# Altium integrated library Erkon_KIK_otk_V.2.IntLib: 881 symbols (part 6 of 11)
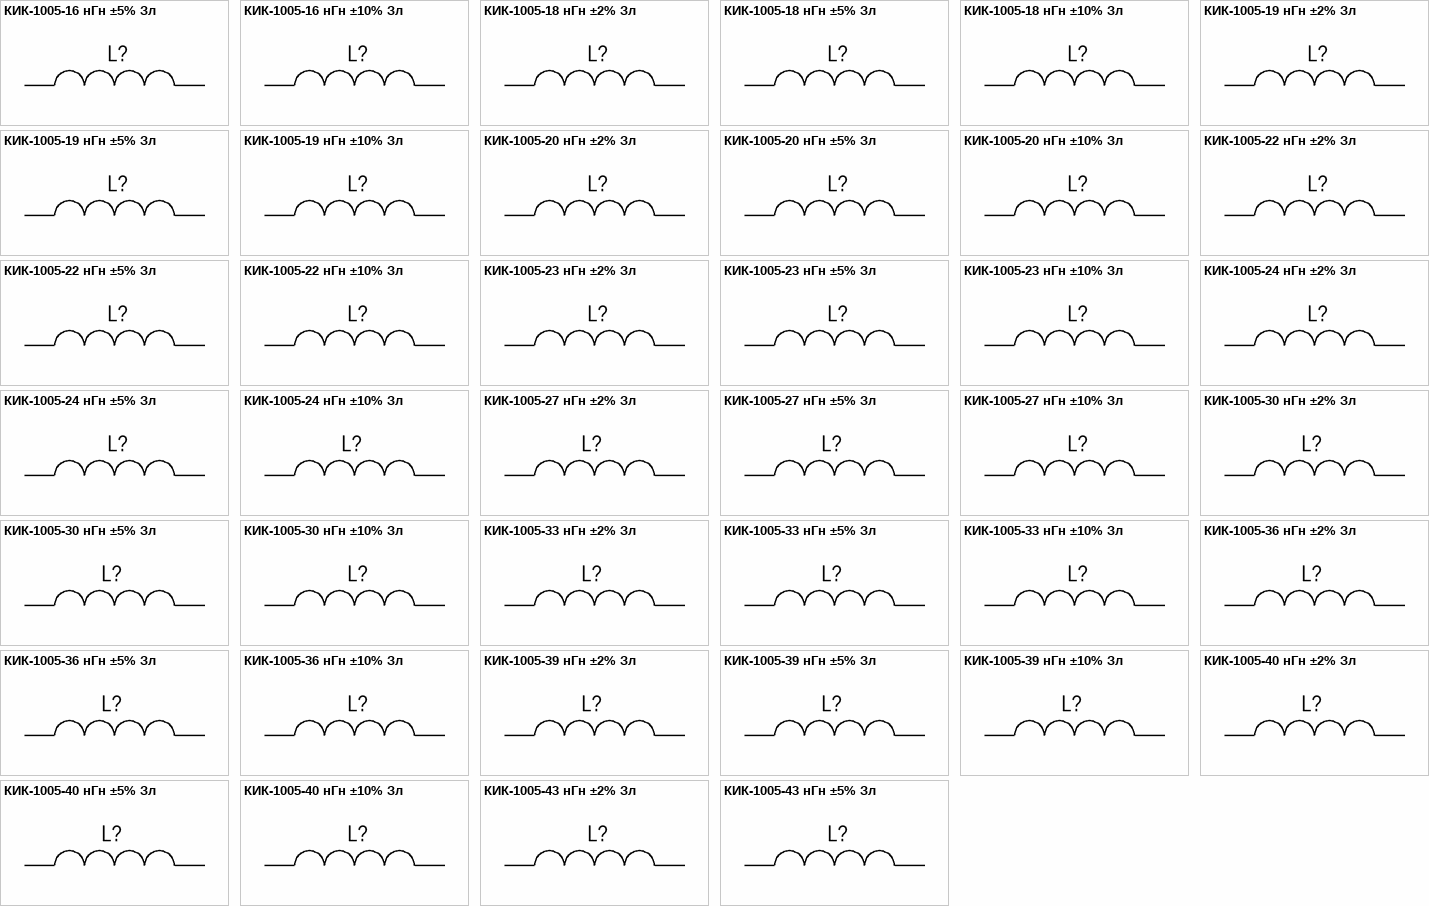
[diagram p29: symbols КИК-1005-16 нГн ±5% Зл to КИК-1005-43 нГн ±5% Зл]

## КИК-1005-20 нГн ±2% Зл
designator L?, comment 20 нГн ±2%  (value not drawn)
Катушка индуктивности с керамическим сердечником и золотым покрытием контактных площадок; Номиналиная индуктивность: 20 нГн; Добротность, не менее: 25; Резонансная частота, не менее: 3.00 ГГц; Сопротивление обмотки постоянноми току, не более: 0.25 Ом; Допустимый ток обмотки: 420 мА; Изготовитель: АО "НПО "ЭРКОН"; Диапазон рабочих температур: от -60 до +125 ℃; Технология монтажа: SMT; Типоразмер: 1005 (0402); Упаковка: Катушка и лента
footprint КИК-1005_Зл (Катушка индуктивности с керамическим сердечником типоразмер 1005(0402))
pins: 1, 2

## КИК-1005-20 нГн ±5% Зл
designator L?, comment 20 нГн ±5%  (value not drawn)
Катушка индуктивности с керамическим сердечником и золотым покрытием контактных площадок; Номиналиная индуктивность: 20 нГн; Добротность, не менее: 25; Резонансная частота, не менее: 3.00 ГГц; Сопротивление обмотки постоянноми току, не более: 0.25 Ом; Допустимый ток обмотки: 420 мА; Изготовитель: АО "НПО "ЭРКОН"; Диапазон рабочих температур: от -60 до +125 ℃; Технология монтажа: SMT; Типоразмер: 1005 (0402); Упаковка: Катушка и лента
footprint КИК-1005_Зл (Катушка индуктивности с керамическим сердечником типоразмер 1005(0402))
pins: 1, 2

## КИК-1005-20 нГн ±10% Зл
designator L?, comment 20 нГн ±10%  (value not drawn)
Катушка индуктивности с керамическим сердечником и золотым покрытием контактных площадок; Номиналиная индуктивность: 20 нГн; Добротность, не менее: 25; Резонансная частота, не менее: 3.00 ГГц; Сопротивление обмотки постоянноми току, не более: 0.25 Ом; Допустимый ток обмотки: 420 мА; Изготовитель: АО "НПО "ЭРКОН"; Диапазон рабочих температур: от -60 до +125 ℃; Технология монтажа: SMT; Типоразмер: 1005 (0402); Упаковка: Катушка и лента
footprint КИК-1005_Зл (Катушка индуктивности с керамическим сердечником типоразмер 1005(0402))
pins: 1, 2

## КИК-1005-22 нГн ±2% Зл
designator L?, comment 22 нГн ±2%  (value not drawn)
Катушка индуктивности с керамическим сердечником и золотым покрытием контактных площадок; Номиналиная индуктивность: 22 нГн; Добротность, не менее: 25; Резонансная частота, не менее: 2.80 ГГц; Сопротивление обмотки постоянноми току, не более: 0.30 Ом; Допустимый ток обмотки: 400 мА; Изготовитель: АО "НПО "ЭРКОН"; Диапазон рабочих температур: от -60 до +125 ℃; Технология монтажа: SMT; Типоразмер: 1005 (0402); Упаковка: Катушка и лента
footprint КИК-1005_Зл (Катушка индуктивности с керамическим сердечником типоразмер 1005(0402))
pins: 1, 2

## КИК-1005-22 нГн ±5% Зл
designator L?, comment 22 нГн ±5%  (value not drawn)
Катушка индуктивности с керамическим сердечником и золотым покрытием контактных площадок; Номиналиная индуктивность: 22 нГн; Добротность, не менее: 25; Резонансная частота, не менее: 2.80 ГГц; Сопротивление обмотки постоянноми току, не более: 0.30 Ом; Допустимый ток обмотки: 400 мА; Изготовитель: АО "НПО "ЭРКОН"; Диапазон рабочих температур: от -60 до +125 ℃; Технология монтажа: SMT; Типоразмер: 1005 (0402); Упаковка: Катушка и лента
footprint КИК-1005_Зл (Катушка индуктивности с керамическим сердечником типоразмер 1005(0402))
pins: 1, 2

## КИК-1005-22 нГн ±10% Зл
designator L?, comment 22 нГн ±10%  (value not drawn)
Катушка индуктивности с керамическим сердечником и золотым покрытием контактных площадок; Номиналиная индуктивность: 22 нГн; Добротность, не менее: 25; Резонансная частота, не менее: 2.80 ГГц; Сопротивление обмотки постоянноми току, не более: 0.30 Ом; Допустимый ток обмотки: 400 мА; Изготовитель: АО "НПО "ЭРКОН"; Диапазон рабочих температур: от -60 до +125 ℃; Технология монтажа: SMT; Типоразмер: 1005 (0402); Упаковка: Катушка и лента
footprint КИК-1005_Зл (Катушка индуктивности с керамическим сердечником типоразмер 1005(0402))
pins: 1, 2

## КИК-1005-23 нГн ±2% Зл
designator L?, comment 23 нГн ±2%  (value not drawn)
Катушка индуктивности с керамическим сердечником и золотым покрытием контактных площадок; Номиналиная индуктивность: 23 нГн; Добротность, не менее: 25; Резонансная частота, не менее: 2.72ГГц; Сопротивление обмотки постоянноми току, не более: 0.30 Ом; Допустимый ток обмотки: 400 мА; Изготовитель: АО "НПО "ЭРКОН"; Диапазон рабочих температур: от -60 до +125 ℃; Технология монтажа: SMT; Типоразмер: 1005 (0402); Упаковка: Катушка и лента
footprint КИК-1005_Зл (Катушка индуктивности с керамическим сердечником типоразмер 1005(0402))
pins: 1, 2

## КИК-1005-23 нГн ±5% Зл
designator L?, comment 23 нГн ±5%  (value not drawn)
Катушка индуктивности с керамическим сердечником и золотым покрытием контактных площадок; Номиналиная индуктивность: 23 нГн; Добротность, не менее: 25; Резонансная частота, не менее: 2.72ГГц; Сопротивление обмотки постоянноми току, не более: 0.30 Ом; Допустимый ток обмотки: 400 мА; Изготовитель: АО "НПО "ЭРКОН"; Диапазон рабочих температур: от -60 до +125 ℃; Технология монтажа: SMT; Типоразмер: 1005 (0402); Упаковка: Катушка и лента
footprint КИК-1005_Зл (Катушка индуктивности с керамическим сердечником типоразмер 1005(0402))
pins: 1, 2

## КИК-1005-23 нГн ±10% Зл
designator L?, comment 23 нГн ±10%  (value not drawn)
Катушка индуктивности с керамическим сердечником и золотым покрытием контактных площадок; Номиналиная индуктивность: 23 нГн; Добротность, не менее: 25; Резонансная частота, не менее: 2.72ГГц; Сопротивление обмотки постоянноми току, не более: 0.30 Ом; Допустимый ток обмотки: 400 мА; Изготовитель: АО "НПО "ЭРКОН"; Диапазон рабочих температур: от -60 до +125 ℃; Технология монтажа: SMT; Типоразмер: 1005 (0402); Упаковка: Катушка и лента
footprint КИК-1005_Зл (Катушка индуктивности с керамическим сердечником типоразмер 1005(0402))
pins: 1, 2

## КИК-1005-24 нГн ±2% Зл
designator L?, comment 24 нГн ±2%  (value not drawn)
Катушка индуктивности с керамическим сердечником и золотым покрытием контактных площадок; Номиналиная индуктивность: 24 нГн; Добротность, не менее: 25; Резонансная частота, не менее: 2.70 ГГц; Сопротивление обмотки постоянноми току, не более: 0.30 Ом; Допустимый ток обмотки: 400 мА; Изготовитель: АО "НПО "ЭРКОН"; Диапазон рабочих температур: от -60 до +125 ℃; Технология монтажа: SMT; Типоразмер: 1005 (0402); Упаковка: Катушка и лента
footprint КИК-1005_Зл (Катушка индуктивности с керамическим сердечником типоразмер 1005(0402))
pins: 1, 2

## КИК-1005-24 нГн ±5% Зл
designator L?, comment 24 нГн ±5%  (value not drawn)
Катушка индуктивности с керамическим сердечником и золотым покрытием контактных площадок; Номиналиная индуктивность: 24 нГн; Добротность, не менее: 25; Резонансная частота, не менее: 2.70 ГГц; Сопротивление обмотки постоянноми току, не более: 0.30 Ом; Допустимый ток обмотки: 400 мА; Изготовитель: АО "НПО "ЭРКОН"; Диапазон рабочих температур: от -60 до +125 ℃; Технология монтажа: SMT; Типоразмер: 1005 (0402); Упаковка: Катушка и лента
footprint КИК-1005_Зл (Катушка индуктивности с керамическим сердечником типоразмер 1005(0402))
pins: 1, 2

## КИК-1005-24 нГн ±10% Зл
designator L?, comment 24 нГн ±10%  (value not drawn)
Катушка индуктивности с керамическим сердечником и золотым покрытием контактных площадок; Номиналиная индуктивность: 24 нГн; Добротность, не менее: 25; Резонансная частота, не менее: 2.70 ГГц; Сопротивление обмотки постоянноми току, не более: 0.30 Ом; Допустимый ток обмотки: 400 мА; Изготовитель: АО "НПО "ЭРКОН"; Диапазон рабочих температур: от -60 до +125 ℃; Технология монтажа: SMT; Типоразмер: 1005 (0402); Упаковка: Катушка и лента
footprint КИК-1005_Зл (Катушка индуктивности с керамическим сердечником типоразмер 1005(0402))
pins: 1, 2

## КИК-1005-27 нГн ±2% Зл
designator L?, comment 27 нГн ±2%  (value not drawn)
Катушка индуктивности с керамическим сердечником и золотым покрытием контактных площадок; Номиналиная индуктивность: 27 нГн; Добротность, не менее: 25; Резонансная частота, не менее: 2.48 ГГц; Сопротивление обмотки постоянноми току, не более: 0.30 Ом; Допустимый ток обмотки: 400 мА; Изготовитель: АО "НПО "ЭРКОН"; Диапазон рабочих температур: от -60 до +125 ℃; Технология монтажа: SMT; Типоразмер: 1005 (0402); Упаковка: Катушка и лента
footprint КИК-1005_Зл (Катушка индуктивности с керамическим сердечником типоразмер 1005(0402))
pins: 1, 2

## КИК-1005-27 нГн ±5% Зл
designator L?, comment 27 нГн ±5%  (value not drawn)
Катушка индуктивности с керамическим сердечником и золотым покрытием контактных площадок; Номиналиная индуктивность: 27 нГн; Добротность, не менее: 25; Резонансная частота, не менее: 2.48 ГГц; Сопротивление обмотки постоянноми току, не более: 0.30 Ом; Допустимый ток обмотки: 400 мА; Изготовитель: АО "НПО "ЭРКОН"; Диапазон рабочих температур: от -60 до +125 ℃; Технология монтажа: SMT; Типоразмер: 1005 (0402); Упаковка: Катушка и лента
footprint КИК-1005_Зл (Катушка индуктивности с керамическим сердечником типоразмер 1005(0402))
pins: 1, 2

## КИК-1005-27 нГн ±10% Зл
designator L?, comment 27 нГн ±10%  (value not drawn)
Катушка индуктивности с керамическим сердечником и золотым покрытием контактных площадок; Номиналиная индуктивность: 27 нГн; Добротность, не менее: 25; Резонансная частота, не менее: 2.48 ГГц; Сопротивление обмотки постоянноми току, не более: 0.30 Ом; Допустимый ток обмотки: 400 мА; Изготовитель: АО "НПО "ЭРКОН"; Диапазон рабочих температур: от -60 до +125 ℃; Технология монтажа: SMT; Типоразмер: 1005 (0402); Упаковка: Катушка и лента
footprint КИК-1005_Зл (Катушка индуктивности с керамическим сердечником типоразмер 1005(0402))
pins: 1, 2

## КИК-1005-30 нГн ±2% Зл
designator L?, comment 30 нГн ±2%  (value not drawn)
Катушка индуктивности с керамическим сердечником и золотым покрытием контактных площадок; Номиналиная индуктивность: 30 нГн; Добротность, не менее: 25; Резонансная частота, не менее: 2.35 ГГц; Сопротивление обмотки постоянноми току, не более: 0.30 Ом; Допустимый ток обмотки: 400 мА; Изготовитель: АО "НПО "ЭРКОН"; Диапазон рабочих температур: от -60 до +125 ℃; Технология монтажа: SMT; Типоразмер: 1005 (0402); Упаковка: Катушка и лента
footprint КИК-1005_Зл (Катушка индуктивности с керамическим сердечником типоразмер 1005(0402))
pins: 1, 2

## КИК-1005-30 нГн ±5% Зл
designator L?, comment 30 нГн ±5%  (value not drawn)
Катушка индуктивности с керамическим сердечником и золотым покрытием контактных площадок; Номиналиная индуктивность: 30 нГн; Добротность, не менее: 25; Резонансная частота, не менее: 2.35 ГГц; Сопротивление обмотки постоянноми току, не более: 0.30 Ом; Допустимый ток обмотки: 400 мА; Изготовитель: АО "НПО "ЭРКОН"; Диапазон рабочих температур: от -60 до +125 ℃; Технология монтажа: SMT; Типоразмер: 1005 (0402); Упаковка: Катушка и лента
footprint КИК-1005_Зл (Катушка индуктивности с керамическим сердечником типоразмер 1005(0402))
pins: 1, 2

## КИК-1005-30 нГн ±10% Зл
designator L?, comment 30 нГн ±10%  (value not drawn)
Катушка индуктивности с керамическим сердечником и золотым покрытием контактных площадок; Номиналиная индуктивность: 30 нГн; Добротность, не менее: 25; Резонансная частота, не менее: 2.35 ГГц; Сопротивление обмотки постоянноми току, не более: 0.30 Ом; Допустимый ток обмотки: 400 мА; Изготовитель: АО "НПО "ЭРКОН"; Диапазон рабочих температур: от -60 до +125 ℃; Технология монтажа: SMT; Типоразмер: 1005 (0402); Упаковка: Катушка и лента
footprint КИК-1005_Зл (Катушка индуктивности с керамическим сердечником типоразмер 1005(0402))
pins: 1, 2

## КИК-1005-33 нГн ±2% Зл
designator L?, comment 33 нГн ±2%  (value not drawn)
Катушка индуктивности с керамическим сердечником и золотым покрытием контактных площадок; Номиналиная индуктивность: 33 нГн; Добротность, не менее: 25; Резонансная частота, не менее: 2.35 ГГц; Сопротивление обмотки постоянноми току, не более: 0.30 Ом; Допустимый ток обмотки: 400 мА; Изготовитель: АО "НПО "ЭРКОН"; Диапазон рабочих температур: от -60 до +125 ℃; Технология монтажа: SMT; Типоразмер: 1005 (0402); Упаковка: Катушка и лента
footprint КИК-1005_Зл (Катушка индуктивности с керамическим сердечником типоразмер 1005(0402))
pins: 1, 2

## КИК-1005-33 нГн ±5% Зл
designator L?, comment 33 нГн ±5%  (value not drawn)
Катушка индуктивности с керамическим сердечником и золотым покрытием контактных площадок; Номиналиная индуктивность: 33 нГн; Добротность, не менее: 25; Резонансная частота, не менее: 2.35 ГГц; Сопротивление обмотки постоянноми току, не более: 0.30 Ом; Допустимый ток обмотки: 400 мА; Изготовитель: АО "НПО "ЭРКОН"; Диапазон рабочих температур: от -60 до +125 ℃; Технология монтажа: SMT; Типоразмер: 1005 (0402); Упаковка: Катушка и лента
footprint КИК-1005_Зл (Катушка индуктивности с керамическим сердечником типоразмер 1005(0402))
pins: 1, 2

## КИК-1005-33 нГн ±10% Зл
designator L?, comment 33 нГн ±10%  (value not drawn)
Катушка индуктивности с керамическим сердечником и золотым покрытием контактных площадок; Номиналиная индуктивность: 33 нГн; Добротность, не менее: 25; Резонансная частота, не менее: 2.35 ГГц; Сопротивление обмотки постоянноми току, не более: 0.30 Ом; Допустимый ток обмотки: 400 мА; Изготовитель: АО "НПО "ЭРКОН"; Диапазон рабочих температур: от -60 до +125 ℃; Технология монтажа: SMT; Типоразмер: 1005 (0402); Упаковка: Катушка и лента
footprint КИК-1005_Зл (Катушка индуктивности с керамическим сердечником типоразмер 1005(0402))
pins: 1, 2

## КИК-1005-36 нГн ±2% Зл
designator L?, comment 36 нГн ±2%  (value not drawn)
Катушка индуктивности с керамическим сердечником и золотым покрытием контактных площадок; Номиналиная индуктивность: 36 нГн; Добротность, не менее: 25; Резонансная частота, не менее: 2.32 ГГц; Сопротивление обмотки постоянноми току, не более: 0.44 Ом; Допустимый ток обмотки: 320 мА; Изготовитель: АО "НПО "ЭРКОН"; Диапазон рабочих температур: от -60 до +125 ℃; Технология монтажа: SMT; Типоразмер: 1005 (0402); Упаковка: Катушка и лента
footprint КИК-1005_Зл (Катушка индуктивности с керамическим сердечником типоразмер 1005(0402))
pins: 1, 2

## КИК-1005-36 нГн ±5% Зл
designator L?, comment 36 нГн ±5%  (value not drawn)
Катушка индуктивности с керамическим сердечником и золотым покрытием контактных площадок; Номиналиная индуктивность: 36 нГн; Добротность, не менее: 25; Резонансная частота, не менее: 2.32 ГГц; Сопротивление обмотки постоянноми току, не более: 0.44 Ом; Допустимый ток обмотки: 320 мА; Изготовитель: АО "НПО "ЭРКОН"; Диапазон рабочих температур: от -60 до +125 ℃; Технология монтажа: SMT; Типоразмер: 1005 (0402); Упаковка: Катушка и лента
footprint КИК-1005_Зл (Катушка индуктивности с керамическим сердечником типоразмер 1005(0402))
pins: 1, 2

## КИК-1005-36 нГн ±10% Зл
designator L?, comment 36 нГн ±10%  (value not drawn)
Катушка индуктивности с керамическим сердечником и золотым покрытием контактных площадок; Номиналиная индуктивность: 36 нГн; Добротность, не менее: 25; Резонансная частота, не менее: 2.32 ГГц; Сопротивление обмотки постоянноми току, не более: 0.44 Ом; Допустимый ток обмотки: 320 мА; Изготовитель: АО "НПО "ЭРКОН"; Диапазон рабочих температур: от -60 до +125 ℃; Технология монтажа: SMT; Типоразмер: 1005 (0402); Упаковка: Катушка и лента
footprint КИК-1005_Зл (Катушка индуктивности с керамическим сердечником типоразмер 1005(0402))
pins: 1, 2

## КИК-1005-39 нГн ±2% Зл
designator L?, comment 39 нГн ±5%  (value not drawn)
Катушка индуктивности с керамическим сердечником и золотым покрытием контактных площадок; Номиналиная индуктивность: 39 нГн; Добротность, не менее: 25; Резонансная частота, не менее: 2.10 ГГц; Сопротивление обмотки постоянноми току, не более: 0.55 Ом; Допустимый ток обмотки: 200 мА; Изготовитель: АО "НПО "ЭРКОН"; Диапазон рабочих температур: от -60 до +125 ℃; Технология монтажа: SMT; Типоразмер: 1005 (0402); Упаковка: Катушка и лента
footprint КИК-1005_Зл (Катушка индуктивности с керамическим сердечником типоразмер 1005(0402))
pins: 1, 2

## КИК-1005-39 нГн ±5% Зл
designator L?, comment 39 нГн ±5%  (value not drawn)
Катушка индуктивности с керамическим сердечником и золотым покрытием контактных площадок; Номиналиная индуктивность: 39 нГн; Добротность, не менее: 25; Резонансная частота, не менее: 2.10 ГГц; Сопротивление обмотки постоянноми току, не более: 0.55 Ом; Допустимый ток обмотки: 200 мА; Изготовитель: АО "НПО "ЭРКОН"; Диапазон рабочих температур: от -60 до +125 ℃; Технология монтажа: SMT; Типоразмер: 1005 (0402); Упаковка: Катушка и лента
footprint КИК-1005_Зл (Катушка индуктивности с керамическим сердечником типоразмер 1005(0402))
pins: 1, 2

## КИК-1005-39 нГн ±10% Зл
designator L?, comment 39 нГн ±10%  (value not drawn)
Катушка индуктивности с керамическим сердечником и золотым покрытием контактных площадок; Номиналиная индуктивность: 39 нГн; Добротность, не менее: 25; Резонансная частота, не менее: 2.10 ГГц; Сопротивление обмотки постоянноми току, не более: 0.55 Ом; Допустимый ток обмотки: 200 мА; Изготовитель: АО "НПО "ЭРКОН"; Диапазон рабочих температур: от -60 до +125 ℃; Технология монтажа: SMT; Типоразмер: 1005 (0402); Упаковка: Катушка и лента
footprint КИК-1005_Зл (Катушка индуктивности с керамическим сердечником типоразмер 1005(0402))
pins: 1, 2

## КИК-1005-40 нГн ±2% Зл
designator L?, comment 40 нГн ±2%  (value not drawn)
Катушка индуктивности с керамическим сердечником и золотым покрытием контактных площадок; Номиналиная индуктивность: 40 нГн; Добротность, не менее: 25; Резонансная частота, не менее: 2.24 ГГц; Сопротивление обмотки постоянноми току, не более: 0.55 Ом; Допустимый ток обмотки: 320 мА; Изготовитель: АО "НПО "ЭРКОН"; Диапазон рабочих температур: от -60 до +125 ℃; Технология монтажа: SMT; Типоразмер: 1005 (0402); Упаковка: Катушка и лента
footprint КИК-1005_Зл (Катушка индуктивности с керамическим сердечником типоразмер 1005(0402))
pins: 1, 2

## КИК-1005-40 нГн ±5% Зл
designator L?, comment 40 нГн ±5%  (value not drawn)
Катушка индуктивности с керамическим сердечником и золотым покрытием контактных площадок; Номиналиная индуктивность: 40 нГн; Добротность, не менее: 25; Резонансная частота, не менее: 2.24 ГГц; Сопротивление обмотки постоянноми току, не более: 0.55 Ом; Допустимый ток обмотки: 320 мА; Изготовитель: АО "НПО "ЭРКОН"; Диапазон рабочих температур: от -60 до +125 ℃; Технология монтажа: SMT; Типоразмер: 1005 (0402); Упаковка: Катушка и лента
footprint КИК-1005_Зл (Катушка индуктивности с керамическим сердечником типоразмер 1005(0402))
pins: 1, 2

## КИК-1005-40 нГн ±10% Зл
designator L?, comment 40 нГн ±10%  (value not drawn)
Катушка индуктивности с керамическим сердечником и золотым покрытием контактных площадок; Номиналиная индуктивность: 40 нГн; Добротность, не менее: 25; Резонансная частота, не менее: 2.24 ГГц; Сопротивление обмотки постоянноми току, не более: 0.55 Ом; Допустимый ток обмотки: 320 мА; Изготовитель: АО "НПО "ЭРКОН"; Диапазон рабочих температур: от -60 до +125 ℃; Технология монтажа: SMT; Типоразмер: 1005 (0402); Упаковка: Катушка и лента
footprint КИК-1005_Зл (Катушка индуктивности с керамическим сердечником типоразмер 1005(0402))
pins: 1, 2

## КИК-1005-43 нГн ±2% Зл
designator L?, comment 43 нГн ±2%  (value not drawn)
Катушка индуктивности с керамическим сердечником и золотым покрытием контактных площадок; Номиналиная индуктивность: 43 нГн; Добротность, не менее: 25; Резонансная частота, не менее: 2.03 ГГц; Сопротивление обмотки постоянноми току, не более: 0.81 Ом; Допустимый ток обмотки: 100 мА; Изготовитель: АО "НПО "ЭРКОН"; Диапазон рабочих температур: от -60 до +125 ℃; Технология монтажа: SMT; Типоразмер: 1005 (0402); Упаковка: Катушка и лента
footprint КИК-1005_Зл (Катушка индуктивности с керамическим сердечником типоразмер 1005(0402))
pins: 1, 2

## КИК-1005-43 нГн ±5% Зл
designator L?, comment 43 нГн ±5%  (value not drawn)
Катушка индуктивности с керамическим сердечником и золотым покрытием контактных площадок; Номиналиная индуктивность: 43 нГн; Добротность, не менее: 25; Резонансная частота, не менее: 2.03 ГГц; Сопротивление обмотки постоянноми току, не более: 0.81 Ом; Допустимый ток обмотки: 100 мА; Изготовитель: АО "НПО "ЭРКОН"; Диапазон рабочих температур: от -60 до +125 ℃; Технология монтажа: SMT; Типоразмер: 1005 (0402); Упаковка: Катушка и лента
footprint КИК-1005_Зл (Катушка индуктивности с керамическим сердечником типоразмер 1005(0402))
pins: 1, 2

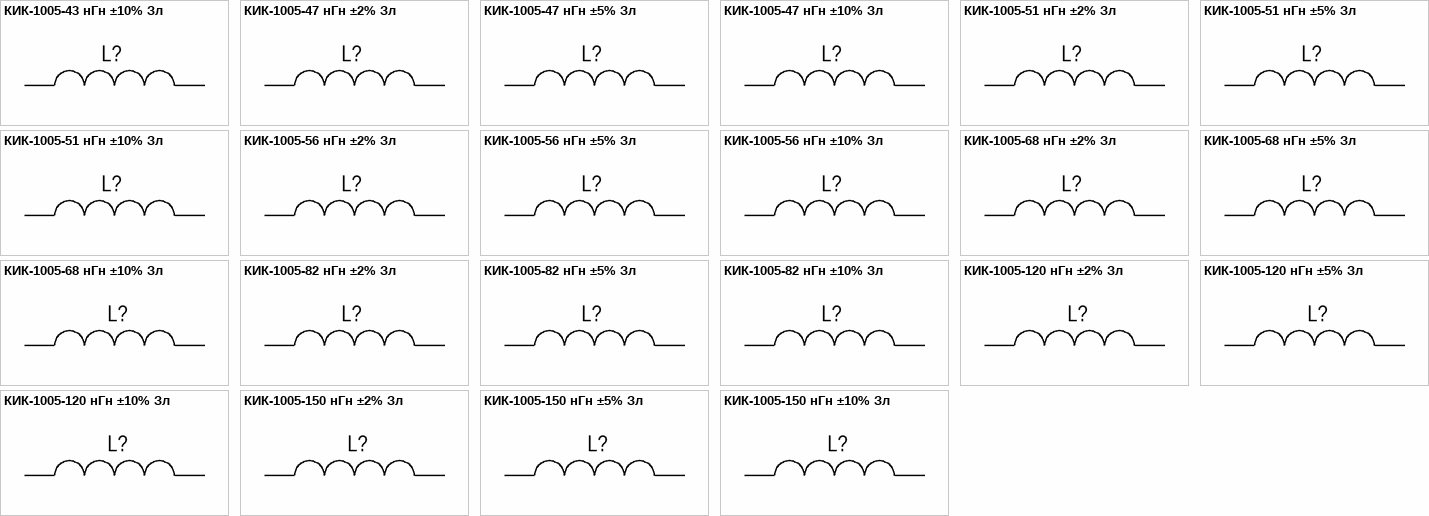
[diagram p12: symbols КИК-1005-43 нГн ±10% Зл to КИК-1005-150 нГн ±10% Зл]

## КИК-1005-43 нГн ±10% Зл
designator L?, comment 43 нГн ±10%  (value not drawn)
Катушка индуктивности с керамическим сердечником и золотым покрытием контактных площадок; Номиналиная индуктивность: 43 нГн; Добротность, не менее: 25; Резонансная частота, не менее: 2.03 ГГц; Сопротивление обмотки постоянноми току, не более: 0.81 Ом; Допустимый ток обмотки: 100 мА; Изготовитель: АО "НПО "ЭРКОН"; Диапазон рабочих температур: от -60 до +125 ℃; Технология монтажа: SMT; Типоразмер: 1005 (0402); Упаковка: Катушка и лента
footprint КИК-1005_Зл (Катушка индуктивности с керамическим сердечником типоразмер 1005(0402))
pins: 1, 2

## КИК-1005-47 нГн ±2% Зл
designator L?, comment 47 нГн ±2%  (value not drawn)
Катушка индуктивности с керамическим сердечником и золотым покрытием контактных площадок; Номиналиная индуктивность: 47 нГн; Добротность, не менее: 25; Резонансная частота, не менее: 2.10 ГГц; Сопротивление обмотки постоянноми току, не более: 0.83 Ом; Допустимый ток обмотки: 150 мА; Изготовитель: АО "НПО "ЭРКОН"; Диапазон рабочих температур: от -60 до +125 ℃; Технология монтажа: SMT; Типоразмер: 1005 (0402); Упаковка: Катушка и лента
footprint КИК-1005_Зл (Катушка индуктивности с керамическим сердечником типоразмер 1005(0402))
pins: 1, 2

## КИК-1005-47 нГн ±5% Зл
designator L?, comment 47 нГн ±5%  (value not drawn)
Катушка индуктивности с керамическим сердечником и золотым покрытием контактных площадок; Номиналиная индуктивность: 47 нГн; Добротность, не менее: 25; Резонансная частота, не менее: 2.10 ГГц; Сопротивление обмотки постоянноми току, не более: 0.83 Ом; Допустимый ток обмотки: 150 мА; Изготовитель: АО "НПО "ЭРКОН"; Диапазон рабочих температур: от -60 до +125 ℃; Технология монтажа: SMT; Типоразмер: 1005 (0402); Упаковка: Катушка и лента
footprint КИК-1005_Зл (Катушка индуктивности с керамическим сердечником типоразмер 1005(0402))
pins: 1, 2

## КИК-1005-47 нГн ±10% Зл
designator L?, comment 47 нГн ±10%  (value not drawn)
Катушка индуктивности с керамическим сердечником и золотым покрытием контактных площадок; Номиналиная индуктивность: 47 нГн; Добротность, не менее: 25; Резонансная частота, не менее: 2.10 ГГц; Сопротивление обмотки постоянноми току, не более: 0.83 Ом; Допустимый ток обмотки: 150 мА; Изготовитель: АО "НПО "ЭРКОН"; Диапазон рабочих температур: от -60 до +125 ℃; Технология монтажа: SMT; Типоразмер: 1005 (0402); Упаковка: Катушка и лента
footprint КИК-1005_Зл (Катушка индуктивности с керамическим сердечником типоразмер 1005(0402))
pins: 1, 2

## КИК-1005-51 нГн ±2% Зл
designator L?, comment 51 нГн ±2%  (value not drawn)
Катушка индуктивности с керамическим сердечником и золотым покрытием контактных площадок; Номиналиная индуктивность: 51 нГн; Добротность, не менее: 25; Резонансная частота, не менее: 1.75 ГГц; Сопротивление обмотки постоянноми току, не более: 0.82 Ом; Допустимый ток обмотки: 100 мА; Изготовитель: АО "НПО "ЭРКОН"; Диапазон рабочих температур: от -60 до +125 ℃; Технология монтажа: SMT; Типоразмер: 1005 (0402); Упаковка: Катушка и лента
footprint КИК-1005_Зл (Катушка индуктивности с керамическим сердечником типоразмер 1005(0402))
pins: 1, 2

## КИК-1005-51 нГн ±5% Зл
designator L?, comment 51 нГн ±5%  (value not drawn)
Катушка индуктивности с керамическим сердечником и золотым покрытием контактных площадок; Номиналиная индуктивность: 51 нГн; Добротность, не менее: 25; Резонансная частота, не менее: 1.75 ГГц; Сопротивление обмотки постоянноми току, не более: 0.82 Ом; Допустимый ток обмотки: 100 мА; Изготовитель: АО "НПО "ЭРКОН"; Диапазон рабочих температур: от -60 до +125 ℃; Технология монтажа: SMT; Типоразмер: 1005 (0402); Упаковка: Катушка и лента
footprint КИК-1005_Зл (Катушка индуктивности с керамическим сердечником типоразмер 1005(0402))
pins: 1, 2

## КИК-1005-51 нГн ±10% Зл
designator L?, comment 51 нГн ±10%  (value not drawn)
Катушка индуктивности с керамическим сердечником и золотым покрытием контактных площадок; Номиналиная индуктивность: 51 нГн; Допускаемое отклонение индуктивности: ±5%; Добротность, не менее: 25; Резонансная частота, не менее: 1.75 ГГц; Сопротивление обмотки постоянноми току, не более: 0.82 Ом; Допустимый ток обмотки: 100 мА; Изготовитель: АО "НПО "ЭРКОН"; Диапазон рабочих температур: от -60 до +125 ℃; Технология монтажа: SMT; Типоразмер: 1005 (0402); Упаковка: Катушка и лента
footprint КИК-1005_Зл (Катушка индуктивности с керамическим сердечником типоразмер 1005(0402))
pins: 1, 2

## КИК-1005-56 нГн ±2% Зл
designator L?, comment 56 нГн ±2%  (value not drawn)
Катушка индуктивности с керамическим сердечником и золотым покрытием контактных площадок; Номиналиная индуктивность: 56 нГн; Добротность, не менее: 22; Резонансная частота, не менее: 1.76 ГГц; Сопротивление обмотки постоянноми току, не более: 0.97 Ом; Допустимый ток обмотки: 100 мА; Изготовитель: АО "НПО "ЭРКОН"; Диапазон рабочих температур: от -60 до +125 ℃; Технология монтажа: SMT; Типоразмер: 1005 (0402); Упаковка: Катушка и лента
footprint КИК-1005_Зл (Катушка индуктивности с керамическим сердечником типоразмер 1005(0402))
pins: 1, 2

## КИК-1005-56 нГн ±5% Зл
designator L?, comment 56 нГн ±5%  (value not drawn)
Катушка индуктивности с керамическим сердечником и золотым покрытием контактных площадок; Номиналиная индуктивность: 56 нГн; Добротность, не менее: 22; Резонансная частота, не менее: 1.76 ГГц; Сопротивление обмотки постоянноми току, не более: 0.97 Ом; Допустимый ток обмотки: 100 мА; Изготовитель: АО "НПО "ЭРКОН"; Диапазон рабочих температур: от -60 до +125 ℃; Технология монтажа: SMT; Типоразмер: 1005 (0402); Упаковка: Катушка и лента
footprint КИК-1005_Зл (Катушка индуктивности с керамическим сердечником типоразмер 1005(0402))
pins: 1, 2

## КИК-1005-56 нГн ±10% Зл
designator L?, comment 56 нГн ±10%  (value not drawn)
Катушка индуктивности с керамическим сердечником и золотым покрытием контактных площадок; Номиналиная индуктивность: 56 нГн; Добротность, не менее: 22; Резонансная частота, не менее: 1.76 ГГц; Сопротивление обмотки постоянноми току, не более: 0.97 Ом; Допустимый ток обмотки: 100 мА; Изготовитель: АО "НПО "ЭРКОН"; Диапазон рабочих температур: от -60 до +125 ℃; Технология монтажа: SMT; Типоразмер: 1005 (0402); Упаковка: Катушка и лента
footprint КИК-1005_Зл (Катушка индуктивности с керамическим сердечником типоразмер 1005(0402))
pins: 1, 2

## КИК-1005-68 нГн ±2% Зл
designator L?, comment 68 нГн ±2%  (value not drawn)
Катушка индуктивности с керамическим сердечником и золотым покрытием контактных площадок; Номиналиная индуктивность: 68 нГн; Добротность, не менее: 22; Резонансная частота, не менее: 1.62ГГц; Сопротивление обмотки постоянноми току, не более: 1.12 Ом; Допустимый ток обмотки: 100 мА; Изготовитель: АО "НПО "ЭРКОН"; Диапазон рабочих температур: от -60 до +125 ℃; Технология монтажа: SMT; Типоразмер: 1005 (0402); Упаковка: Катушка и лента
footprint КИК-1005_Зл (Катушка индуктивности с керамическим сердечником типоразмер 1005(0402))
pins: 1, 2

## КИК-1005-68 нГн ±5% Зл
designator L?, comment 68 нГн ±5%  (value not drawn)
Катушка индуктивности с керамическим сердечником и золотым покрытием контактных площадок; Номиналиная индуктивность: 68 нГн; Добротность, не менее: 22; Резонансная частота, не менее: 1.62ГГц; Сопротивление обмотки постоянноми току, не более: 1.12 Ом; Допустимый ток обмотки: 100 мА; Изготовитель: АО "НПО "ЭРКОН"; Диапазон рабочих температур: от -60 до +125 ℃; Технология монтажа: SMT; Типоразмер: 1005 (0402); Упаковка: Катушка и лента
footprint КИК-1005_Зл (Катушка индуктивности с керамическим сердечником типоразмер 1005(0402))
pins: 1, 2

## КИК-1005-68 нГн ±10% Зл
designator L?, comment 68 нГн ±10%  (value not drawn)
Катушка индуктивности с керамическим сердечником и золотым покрытием контактных площадок; Номиналиная индуктивность: 68 нГн; Добротность, не менее: 22; Резонансная частота, не менее: 1.62ГГц; Сопротивление обмотки постоянноми току, не более: 1.12 Ом; Допустимый ток обмотки: 100 мА; Изготовитель: АО "НПО "ЭРКОН"; Диапазон рабочих температур: от -60 до +125 ℃; Технология монтажа: SMT; Типоразмер: 1005 (0402); Упаковка: Катушка и лента
footprint КИК-1005_Зл (Катушка индуктивности с керамическим сердечником типоразмер 1005(0402))
pins: 1, 2

## КИК-1005-82 нГн ±2% Зл
designator L?, comment 82 нГн ±2%  (value not drawn)
Катушка индуктивности с керамическим сердечником и золотым покрытием контактных площадок; Номиналиная индуктивность: 82 нГн; Добротность, не менее: 20; Резонансная частота, не менее: 1.26 ГГц; Сопротивление обмотки постоянноми току, не более: 1.55 Ом; Допустимый ток обмотки: 50 мА; Изготовитель: АО "НПО "ЭРКОН"; Диапазон рабочих температур: от -60 до +125 ℃; Технология монтажа: SMT; Типоразмер: 1005 (0402); Упаковка: Катушка и лента
footprint КИК-1005_Зл (Катушка индуктивности с керамическим сердечником типоразмер 1005(0402))
pins: 1, 2

## КИК-1005-82 нГн ±5% Зл
designator L?, comment 82 нГн ±5%  (value not drawn)
Катушка индуктивности с керамическим сердечником и золотым покрытием контактных площадок; Номиналиная индуктивность: 82 нГн; Добротность, не менее: 20; Резонансная частота, не менее: 1.26 ГГц; Сопротивление обмотки постоянноми току, не более: 1.55 Ом; Допустимый ток обмотки: 50 мА; Изготовитель: АО "НПО "ЭРКОН"; Диапазон рабочих температур: от -60 до +125 ℃; Технология монтажа: SMT; Типоразмер: 1005 (0402); Упаковка: Катушка и лента
footprint КИК-1005_Зл (Катушка индуктивности с керамическим сердечником типоразмер 1005(0402))
pins: 1, 2

## КИК-1005-82 нГн ±10% Зл
designator L?, comment 82 нГн ±10%  (value not drawn)
Катушка индуктивности с керамическим сердечником и золотым покрытием контактных площадок; Номиналиная индуктивность: 82 нГн; Добротность, не менее: 20; Резонансная частота, не менее: 1.26 ГГц; Сопротивление обмотки постоянноми току, не более: 1.55 Ом; Допустимый ток обмотки: 50 мА; Изготовитель: АО "НПО "ЭРКОН"; Диапазон рабочих температур: от -60 до +125 ℃; Технология монтажа: SMT; Типоразмер: 1005 (0402); Упаковка: Катушка и лента
footprint КИК-1005_Зл (Катушка индуктивности с керамическим сердечником типоразмер 1005(0402))
pins: 1, 2

## КИК-1005-120 нГн ±2% Зл
designator L?, comment 120 нГн ±2%  (value not drawn)
Катушка индуктивности с керамическим сердечником и золотым покрытием контактных площадок; Номиналиная индуктивность: 120 нГн; Добротность, не менее: 20; Резонансная частота, не менее: 1.8 ГГц; Сопротивление обмотки постоянноми току, не более: 1,45 Ом; Допустимый ток обмотки: 200 мА; Изготовитель: АО "НПО "ЭРКОН"; Диапазон рабочих температур: от -60 до +125 ℃; Технология монтажа: SMT; Типоразмер: 1005 (0402); Упаковка: Катушка и лента
footprint КИК-1005_Зл (Катушка индуктивности с керамическим сердечником типоразмер 1005(0402))
pins: 1, 2

## КИК-1005-120 нГн ±5% Зл
designator L?, comment 120 нГн ±5%  (value not drawn)
Катушка индуктивности с керамическим сердечником и золотым покрытием контактных площадок; Номиналиная индуктивность: 120 нГн; Добротность, не менее: 20; Резонансная частота, не менее: 1.8 ГГц; Сопротивление обмотки постоянноми току, не более: 1,45 Ом; Допустимый ток обмотки: 200 мА; Изготовитель: АО "НПО "ЭРКОН"; Диапазон рабочих температур: от -60 до +125 ℃; Технология монтажа: SMT; Типоразмер: 1005 (0402); Упаковка: Катушка и лента
footprint КИК-1005_Зл (Катушка индуктивности с керамическим сердечником типоразмер 1005(0402))
pins: 1, 2

## КИК-1005-120 нГн ±10% Зл
designator L?, comment 120 нГн ±10%  (value not drawn)
Катушка индуктивности с керамическим сердечником и золотым покрытием контактных площадок; Номиналиная индуктивность: 120 нГн; Добротность, не менее: 22; Резонансная частота, не менее: 1.8 ГГц; Сопротивление обмотки постоянноми току, не более: 1,45 Ом; Допустимый ток обмотки: 200 мА; Изготовитель: АО "НПО "ЭРКОН"; Диапазон рабочих температур: от -60 до +125 ℃; Технология монтажа: SMT; Типоразмер: 1005 (0402); Упаковка: Катушка и лента
footprint КИК-1005_Зл (Катушка индуктивности с керамическим сердечником типоразмер 1005(0402))
pins: 1, 2

## КИК-1005-150 нГн ±2% Зл
designator L?, comment 150 нГн ±2%  (value not drawn)
Катушка индуктивности с керамическим сердечником и золотым покрытием контактных площадок; Номиналиная индуктивность: 150 нГн; Добротность, не менее: 20; Резонансная частота, не менее: 1.70 ГГц; Сопротивление обмотки постоянноми току, не более: 2.10 Ом; Допустимый ток обмотки: 200 мА; Изготовитель: АО "НПО "ЭРКОН"; Диапазон рабочих температур: от -60 до +125 ℃; Технология монтажа: SMT; Типоразмер: 1005 (0402); Упаковка: Катушка и лента
footprint КИК-1005_Зл (Катушка индуктивности с керамическим сердечником типоразмер 1005(0402))
pins: 1, 2

## КИК-1005-150 нГн ±5% Зл
designator L?, comment 150 нГн ±5%  (value not drawn)
Катушка индуктивности с керамическим сердечником и золотым покрытием контактных площадок; Номиналиная индуктивность: 150 нГн; Добротность, не менее: 20; Резонансная частота, не менее: 1.70 ГГц; Сопротивление обмотки постоянноми току, не более: 2.10 Ом; Допустимый ток обмотки: 200 мА; Изготовитель: АО "НПО "ЭРКОН"; Диапазон рабочих температур: от -60 до +125 ℃; Технология монтажа: SMT; Типоразмер: 1005 (0402); Упаковка: Катушка и лента
footprint КИК-1005_Зл (Катушка индуктивности с керамическим сердечником типоразмер 1005(0402))
pins: 1, 2

## КИК-1005-150 нГн ±10% Зл
designator L?, comment 150 нГн ±10%  (value not drawn)
Катушка индуктивности с керамическим сердечником и золотым покрытием контактных площадок; Номиналиная индуктивность: 150 нГн; Добротность, не менее: 20; Резонансная частота, не менее: 1.70 ГГц; Сопротивление обмотки постоянноми току, не более: 2.10 Ом; Допустимый ток обмотки: 50 мА; Изготовитель: АО "НПО "ЭРКОН"; Диапазон рабочих температур: от -60 до +125 ℃; Технология монтажа: SMT; Типоразмер: 1005 (0402); Упаковка: Катушка и лента
footprint КИК-1005_Зл (Катушка индуктивности с керамическим сердечником типоразмер 1005(0402))
pins: 1, 2


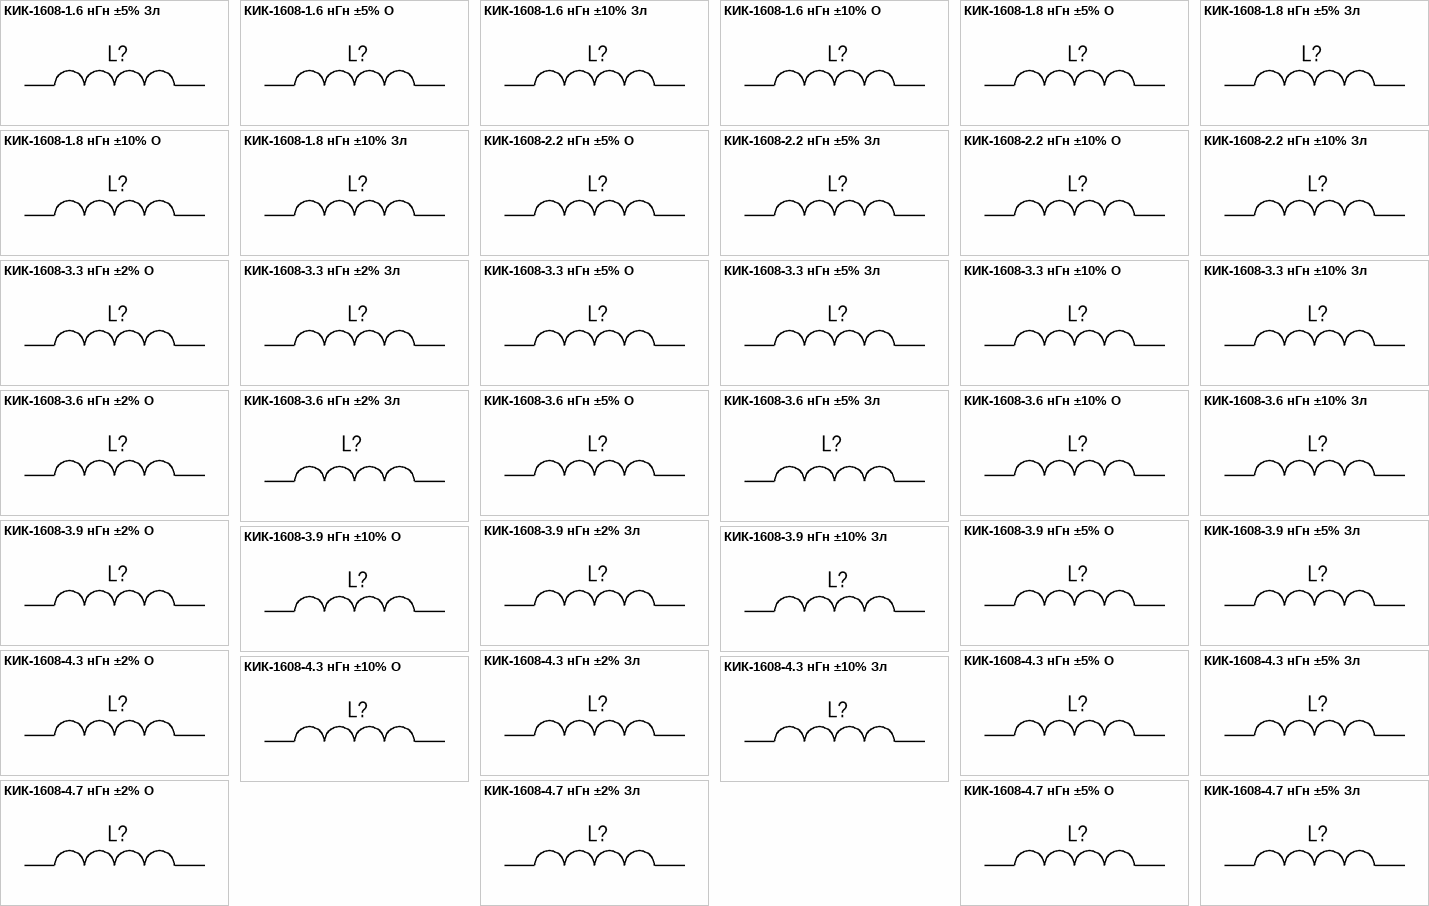
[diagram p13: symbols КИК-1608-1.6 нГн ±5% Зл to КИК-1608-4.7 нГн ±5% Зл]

## КИК-1608-1.6 нГн ±5% Зл
designator L?, comment 1.8 нГн ±5%  (value not drawn)
Катушка индуктивности с керамическим сердечником и золотым покрытием контактных площадок; Номиналиная индуктивность: 1.6 нГн; Добротность, не менее: 16; Резонансная частота, не менее: 12.5 ГГц; Сопротивление обмотки постоянноми току, не более: 0.030 Ом; Допустимый ток обмотки: 700 мА; Диапазон рабочих температур: от -60 до +125 ℃; Упаковка: Катушка и лента; Типоразмер: 1608 (0603); Технология монтажа: SMT; Изготовитель: АО "НПО "ЭРКОН"
footprint КИК-1608_Зл (Катушка индуктивности с керамическим сердечником  типоразмер 1005(0402))
pins: 1, 2

## КИК-1608-1.6 нГн ±5% О
designator L?, comment 1 нГн ±5%  (value not drawn)
Катушка индуктивности с керамическим сердечником и  финишным покрытием контактных площадок оловом; Номиналиная индуктивность: 1.6 нГн; Добротность, не менее: 16; Резонансная частота, не менее: 12.5 ГГц; Сопротивление обмотки постоянноми току, не более: 0.030 Ом; Допустимый ток обмотки: 700 мА; Диапазон рабочих температур: от -60 до +125 ℃; Упаковка: Катушка и лента; Типоразмер: 1608 (0603); Технология монтажа: SMT; Изготовитель: АО "НПО "ЭРКОН"
footprint КИК-1608_О (Катушка индуктивности с керамическим сердечником  типоразмер 1005(0402))
pins: 1, 2

## КИК-1608-1.6 нГн ±10% Зл
designator L?, comment 1.6 нГн ±10%  (value not drawn)
Катушка индуктивности с керамическим сердечником и золотым покрытием контактных площадок; Номиналиная индуктивность: 1.6 нГн; Добротность, не менее: 16; Резонансная частота, не менее: 12.5 ГГц; Сопротивление обмотки постоянноми току, не более: 0.030 Ом; Допустимый ток обмотки: 700 мА; Диапазон рабочих температур: от -60 до +125 ℃; Упаковка: Катушка и лента; Типоразмер: 1608 (0603); Технология монтажа: SMT; Изготовитель: АО "НПО "ЭРКОН"
footprint КИК-1608_Зл (Катушка индуктивности с керамическим сердечником  типоразмер 1005(0402))
pins: 1, 2

## КИК-1608-1.6 нГн ±10% О
designator L?, comment 1.6 нГн ±10%  (value not drawn)
Катушка индуктивности с керамическим сердечником и  финишным покрытием контактных площадок оловом; Номиналиная индуктивность: 1.6 нГн; Добротность, не менее: 16; Резонансная частота, не менее: 12.5 ГГц; Сопротивление обмотки постоянноми току, не более: 0.030 Ом; Допустимый ток обмотки: 700 мА; Диапазон рабочих температур: от -60 до +125 ℃; Упаковка: Катушка и лента; Типоразмер: 1608 (0603); Технология монтажа: SMT; Изготовитель: АО "НПО "ЭРКОН"
footprint КИК-1608_О (Катушка индуктивности с керамическим сердечником  типоразмер 1005(0402))
pins: 1, 2

## КИК-1608-1.8 нГн ±5% O
designator L?, comment 1.8 нГн ±5%  (value not drawn)
Катушка индуктивности с керамическим сердечником и  финишным покрытием контактных площадок оловом; Номиналиная индуктивность: 1.8 нГн; Добротность, не менее: 16; Резонансная частота, не менее: 12.5 ГГц; Сопротивление обмотки постоянноми току, не более: 0.045 Ом; Допустимый ток обмотки: 700 мА; Диапазон рабочих температур: от -60 до +125 ℃; Упаковка: Катушка и лента; Типоразмер: 1608 (0603); Технология монтажа: SMT; Изготовитель: АО "НПО "ЭРКОН"
footprint КИК-1608_О (Катушка индуктивности с керамическим сердечником  типоразмер 1005(0402))
pins: 1, 2

## КИК-1608-1.8 нГн ±5% Зл
designator L?, comment 1.8 нГн ±5%  (value not drawn)
Катушка индуктивности с керамическим сердечником и золотым покрытием контактных площадок; Номиналиная индуктивность: 1.8 нГн; Добротность, не менее: 16; Резонансная частота, не менее: 12.5 ГГц; Сопротивление обмотки постоянноми току, не более: 0.045 Ом; Допустимый ток обмотки: 700 мА; Диапазон рабочих температур: от -60 до +125 ℃; Упаковка: Катушка и лента; Типоразмер: 1608 (0603); Технология монтажа: SMT; Изготовитель: АО "НПО "ЭРКОН"
footprint КИК-1608_Зл (Катушка индуктивности с керамическим сердечником  типоразмер 1005(0402))
pins: 1, 2

## КИК-1608-1.8 нГн ±10% O
designator L?, comment 1.8 нГн ±10%  (value not drawn)
Катушка индуктивности с керамическим сердечником и  финишным покрытием контактных площадок оловом; Номиналиная индуктивность: 1.8 нГн; Добротность, не менее: 16; Резонансная частота, не менее: 12.5 ГГц; Сопротивление обмотки постоянноми току, не более: 0.045 Ом; Допустимый ток обмотки: 700 мА; Диапазон рабочих температур: от -60 до +125 ℃; Упаковка: Катушка и лента; Типоразмер: 1608 (0603); Технология монтажа: SMT; Изготовитель: АО "НПО "ЭРКОН"
footprint КИК-1608_О (Катушка индуктивности с керамическим сердечником  типоразмер 1005(0402))
pins: 1, 2

## КИК-1608-1.8 нГн ±10% Зл
designator L?, comment 1.8 нГн ±10%  (value not drawn)
Катушка индуктивности с керамическим сердечником и золотым покрытием контактных площадок; Номиналиная индуктивность: 1.8 нГн; Добротность, не менее: 16; Резонансная частота, не менее: 12.5 ГГц; Сопротивление обмотки постоянноми току, не более: 0.045 Ом; Допустимый ток обмотки: 700 мА; Диапазон рабочих температур: от -60 до +125 ℃; Упаковка: Катушка и лента; Типоразмер: 1608 (0603); Технология монтажа: SMT; Изготовитель: АО "НПО "ЭРКОН"
footprint КИК-1608_Зл (Катушка индуктивности с керамическим сердечником  типоразмер 1005(0402))
pins: 1, 2

## КИК-1608-2.2 нГн ±5% O
designator L?, comment 2.2 нГн ±5%  (value not drawn)
Катушка индуктивности с керамическим сердечником и  финишным покрытием контактных площадок оловом; Номиналиная индуктивность: 2.2 нГн; Добротность, не менее: 16; Резонансная частота, не менее: 12.5 ГГц; Сопротивление обмотки постоянноми току, не более: 0.250 Ом; Допустимый ток обмотки: 100 мА; Диапазон рабочих температур: от -60 до +125 ℃; Упаковка: Катушка и лента; Типоразмер: 1608 (0603); Технология монтажа: SMT; Изготовитель: АО "НПО "ЭРКОН"
footprint КИК-1608_О (Катушка индуктивности с керамическим сердечником  типоразмер 1005(0402))
pins: 1, 2

## КИК-1608-2.2 нГн ±5% Зл
designator L?, comment 2.2 нГн ±5%  (value not drawn)
Катушка индуктивности с керамическим сердечником и золотым покрытием контактных площадок; Номиналиная индуктивность: 2.2 нГн; Добротность, не менее: 16; Резонансная частота, не менее: 12.5 ГГц; Сопротивление обмотки постоянноми току, не более: 0.250 Ом; Допустимый ток обмотки: 100 мА; Диапазон рабочих температур: от -60 до +125 ℃; Упаковка: Катушка и лента; Типоразмер: 1608 (0603); Технология монтажа: SMT; Изготовитель: АО "НПО "ЭРКОН"
footprint КИК-1608_Зл (Катушка индуктивности с керамическим сердечником  типоразмер 1005(0402))
pins: 1, 2

## КИК-1608-2.2 нГн ±10% O
designator L?, comment 2.2 нГн ±10%  (value not drawn)
Катушка индуктивности с керамическим сердечником и  финишным покрытием контактных площадок оловом; Номиналиная индуктивность: 2.2 нГн; Добротность, не менее: 16; Резонансная частота, не менее: 12.5 ГГц; Сопротивление обмотки постоянноми току, не более: 0.250 Ом; Допустимый ток обмотки: 100 мА; Диапазон рабочих температур: от -60 до +125 ℃; Упаковка: Катушка и лента; Типоразмер: 1608 (0603); Технология монтажа: SMT; Изготовитель: АО "НПО "ЭРКОН"
footprint КИК-1608_О (Катушка индуктивности с керамическим сердечником  типоразмер 1005(0402))
pins: 1, 2

## КИК-1608-2.2 нГн ±10% Зл
designator L?, comment 2.2 нГн ±10%  (value not drawn)
Катушка индуктивности с керамическим сердечником и золотым покрытием контактных площадок; Номиналиная индуктивность: 2.2 нГн; Добротность, не менее: 16; Резонансная частота, не менее: 12.5 ГГц; Сопротивление обмотки постоянноми току, не более: 0.250 Ом; Допустимый ток обмотки: 100 мА; Диапазон рабочих температур: от -60 до +125 ℃; Упаковка: Катушка и лента; Типоразмер: 1608 (0603); Технология монтажа: SMT; Изготовитель: АО "НПО "ЭРКОН"
footprint КИК-1608_Зл (Катушка индуктивности с керамическим сердечником  типоразмер 1005(0402))
pins: 1, 2

## КИК-1608-3.3 нГн ±2% O
designator L?, comment 3.3 нГн ±2%  (value not drawn)
Катушка индуктивности с керамическим сердечником и  финишным покрытием контактных площадок оловом; Номиналиная индуктивность: 3.3 нГн; Добротность, не менее: 16; Резонансная частота, не менее: 5.90 ГГц; Сопротивление обмотки постоянноми току, не более: 0.045 Ом; Допустимый ток обмотки: 700 мА; Диапазон рабочих температур: от -60 до +125 ℃; Упаковка: Катушка и лента; Типоразмер: 1608 (0603); Технология монтажа: SMT; Изготовитель: АО "НПО "ЭРКОН"
footprint КИК-1608_О (Катушка индуктивности с керамическим сердечником  типоразмер 1005(0402))
pins: 1, 2

## КИК-1608-3.3 нГн ±2% Зл
designator L?, comment 3.3 нГн ±2%  (value not drawn)
Катушка индуктивности с керамическим сердечником и золотым покрытием контактных площадок; Номиналиная индуктивность: 3.3 нГн; Добротность, не менее: 16; Резонансная частота, не менее: 5.90 ГГц; Сопротивление обмотки постоянноми току, не более: 0.045 Ом; Допустимый ток обмотки: 700 мА; Диапазон рабочих температур: от -60 до +125 ℃; Упаковка: Катушка и лента; Типоразмер: 1608 (0603); Технология монтажа: SMT; Изготовитель: АО "НПО "ЭРКОН"
footprint КИК-1608_Зл (Катушка индуктивности с керамическим сердечником  типоразмер 1005(0402))
pins: 1, 2

## КИК-1608-3.3 нГн ±5% O
designator L?, comment 3.3 нГн ±5%  (value not drawn)
Катушка индуктивности с керамическим сердечником и  финишным покрытием контактных площадок оловом; Номиналиная индуктивность: 3.3 нГн; Добротность, не менее: 16; Резонансная частота, не менее: 5.90 ГГц; Сопротивление обмотки постоянноми току, не более: 0.045 Ом; Допустимый ток обмотки: 700 мА; Диапазон рабочих температур: от -60 до +125 ℃; Упаковка: Катушка и лента; Типоразмер: 1608 (0603); Технология монтажа: SMT; Изготовитель: АО "НПО "ЭРКОН"
footprint КИК-1608_О (Катушка индуктивности с керамическим сердечником  типоразмер 1005(0402))
pins: 1, 2

## КИК-1608-3.3 нГн ±5% Зл
designator L?, comment 3.3 нГн ±5%  (value not drawn)
Катушка индуктивности с керамическим сердечником и золотым покрытием контактных площадок; Номиналиная индуктивность: 3.3 нГн; Добротность, не менее: 16; Резонансная частота, не менее: 5.90 ГГц; Сопротивление обмотки постоянноми току, не более: 0.045 Ом; Допустимый ток обмотки: 700 мА; Диапазон рабочих температур: от -60 до +125 ℃; Упаковка: Катушка и лента; Типоразмер: 1608 (0603); Технология монтажа: SMT; Изготовитель: АО "НПО "ЭРКОН"
footprint КИК-1608_Зл (Катушка индуктивности с керамическим сердечником  типоразмер 1005(0402))
pins: 1, 2

## КИК-1608-3.3 нГн ±10% O
designator L?, comment 3.3 нГн ±10%  (value not drawn)
Катушка индуктивности с керамическим сердечником и  финишным покрытием контактных площадок оловом; Номиналиная индуктивность: 3.3 нГн; Добротность, не менее: 16; Резонансная частота, не менее: 5.90 ГГц; Сопротивление обмотки постоянноми току, не более: 0.045 Ом; Допустимый ток обмотки: 700 мА; Диапазон рабочих температур: от -60 до +125 ℃; Упаковка: Катушка и лента; Типоразмер: 1608 (0603); Технология монтажа: SMT; Изготовитель: АО "НПО "ЭРКОН"
footprint КИК-1608_О (Катушка индуктивности с керамическим сердечником  типоразмер 1005(0402))
pins: 1, 2

## КИК-1608-3.3 нГн ±10% Зл
designator L?, comment 3.3 нГн ±10%  (value not drawn)
Катушка индуктивности с керамическим сердечником и золотым покрытием контактных площадок; Номиналиная индуктивность: 3.3 нГн; Добротность, не менее: 16; Резонансная частота, не менее: 5.90 ГГц; Сопротивление обмотки постоянноми току, не более: 0.045 Ом; Допустимый ток обмотки: 700 мА; Диапазон рабочих температур: от -60 до +125 ℃; Упаковка: Катушка и лента; Типоразмер: 1608 (0603); Технология монтажа: SMT; Изготовитель: АО "НПО "ЭРКОН"
footprint КИК-1608_Зл (Катушка индуктивности с керамическим сердечником  типоразмер 1005(0402))
pins: 1, 2

## КИК-1608-3.6 нГн ±2% O
designator L?, comment 3.6 нГн ±2%  (value not drawn)
Катушка индуктивности с керамическим сердечником и  финишным покрытием контактных площадок оловом; Номиналиная индуктивность: 3.6 нГн; Добротность, не менее: 16; Резонансная частота, не менее: 5.90 ГГц; Сопротивление обмотки постоянноми току, не более: 0.063 Ом; Допустимый ток обмотки: 700 мА; Диапазон рабочих температур: от -60 до +125 ℃; Упаковка: Катушка и лента; Типоразмер: 1608 (0603); Технология монтажа: SMT; Изготовитель: АО "НПО "ЭРКОН"
footprint КИК-1608_О (Катушка индуктивности с керамическим сердечником  типоразмер 1005(0402))
pins: 1, 2

## КИК-1608-3.6 нГн ±2% Зл
designator L?, comment 3.6 нГн ±2%  (value not drawn)
Катушка индуктивности с керамическим сердечником и золотым покрытием контактных площадок; Номиналиная индуктивность: 3.6 нГн; Добротность, не менее: 16; Резонансная частота, не менее: 5.90 ГГц; Сопротивление обмотки постоянноми току, не более: 0.063 Ом; Допустимый ток обмотки: 700 мА; Диапазон рабочих температур: от -60 до +125 ℃; Упаковка: Катушка и лента; Типоразмер: 1608 (0603); Технология монтажа: SMT; Изготовитель: АО "НПО "ЭРКОН"
footprint КИК-1608_Зл (Катушка индуктивности с керамическим сердечником  типоразмер 1005(0402))
pins: 1, 2

## КИК-1608-3.6 нГн ±5% O
designator L?, comment 3.6 нГн ±5%  (value not drawn)
Катушка индуктивности с керамическим сердечником и  финишным покрытием контактных площадок оловом; Номиналиная индуктивность: 3.6 нГн; Добротность, не менее: 16; Резонансная частота, не менее: 5.90 ГГц; Сопротивление обмотки постоянноми току, не более: 0.063 Ом; Допустимый ток обмотки: 700 мА; Диапазон рабочих температур: от -60 до +125 ℃; Упаковка: Катушка и лента; Типоразмер: 1608 (0603); Технология монтажа: SMT; Изготовитель: АО "НПО "ЭРКОН"
footprint КИК-1608_О (Катушка индуктивности с керамическим сердечником  типоразмер 1005(0402))
pins: 1, 2

## КИК-1608-3.6 нГн ±5% Зл
designator L?, comment 3.6 нГн ±5%  (value not drawn)
Катушка индуктивности с керамическим сердечником и золотым покрытием контактных площадок; Номиналиная индуктивность: 3.6 нГн; Добротность, не менее: 16; Резонансная частота, не менее: 5.90 ГГц; Сопротивление обмотки постоянноми току, не более: 0.063 Ом; Допустимый ток обмотки: 700 мА; Диапазон рабочих температур: от -60 до +125 ℃; Упаковка: Катушка и лента; Типоразмер: 1608 (0603); Технология монтажа: SMT; Изготовитель: АО "НПО "ЭРКОН"
footprint КИК-1608_Зл (Катушка индуктивности с керамическим сердечником  типоразмер 1005(0402))
pins: 1, 2

## КИК-1608-3.6 нГн ±10% O
designator L?, comment 3.6 нГн ±10%  (value not drawn)
Катушка индуктивности с керамическим сердечником и  финишным покрытием контактных площадок оловом; Номиналиная индуктивность: 3.6 нГн; Добротность, не менее: 16; Резонансная частота, не менее: 5.90 ГГц; Сопротивление обмотки постоянноми току, не более: 0.063 Ом; Допустимый ток обмотки: 700 мА; Диапазон рабочих температур: от -60 до +125 ℃; Упаковка: Катушка и лента; Типоразмер: 1608 (0603); Технология монтажа: SMT; Изготовитель: АО "НПО "ЭРКОН"
footprint КИК-1608_О (Катушка индуктивности с керамическим сердечником  типоразмер 1005(0402))
pins: 1, 2

## КИК-1608-3.6 нГн ±10% Зл
designator L?, comment 3.6 нГн ±10%  (value not drawn)
Катушка индуктивности с керамическим сердечником и золотым покрытием контактных площадок; Номиналиная индуктивность: 3.6 нГн; Добротность, не менее: 16; Резонансная частота, не менее: 5.90 ГГц; Сопротивление обмотки постоянноми току, не более: 0.063 Ом; Допустимый ток обмотки: 700 мА; Диапазон рабочих температур: от -60 до +125 ℃; Упаковка: Катушка и лента; Типоразмер: 1608 (0603); Технология монтажа: SMT; Изготовитель: АО "НПО "ЭРКОН"
footprint КИК-1608_Зл (Катушка индуктивности с керамическим сердечником  типоразмер 1005(0402))
pins: 1, 2

## КИК-1608-3.9 нГн ±2% O
designator L?, comment 3.9 нГн ±2%  (value not drawn)
Катушка индуктивности с керамическим сердечником и  финишным покрытием контактных площадок оловом; Номиналиная индуктивность: 3.9 нГн; Добротность, не менее: 16; Резонансная частота, не менее: 6.90 ГГц; Сопротивление обмотки постоянноми току, не более: 0.080 Ом; Допустимый ток обмотки: 700 мА; Диапазон рабочих температур: от -60 до +125 ℃; Упаковка: Катушка и лента; Типоразмер: 1608 (0603); Технология монтажа: SMT; Изготовитель: АО "НПО "ЭРКОН"
footprint КИК-1608_О (Катушка индуктивности с керамическим сердечником  типоразмер 1005(0402))
pins: 1, 2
